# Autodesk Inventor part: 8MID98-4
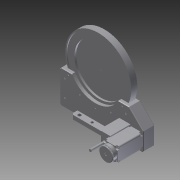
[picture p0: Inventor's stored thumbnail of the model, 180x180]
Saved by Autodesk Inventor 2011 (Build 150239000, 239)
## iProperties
Created: 2011-04
Part Number: 8MID98-4
Document SubType Name: Modeling
Designer: vadybininkas6
Density: 1 g/cm^3
Author: vadybininkas6
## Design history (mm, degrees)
feature "Base1"
body "Solid1"
